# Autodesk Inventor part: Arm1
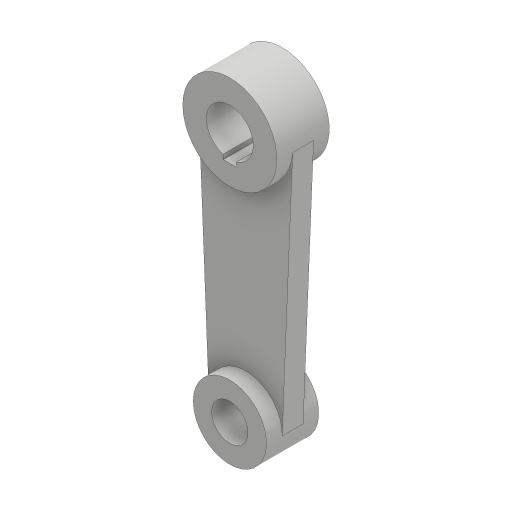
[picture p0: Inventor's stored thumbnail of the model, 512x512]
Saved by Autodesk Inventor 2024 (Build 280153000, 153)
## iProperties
Created: 2016-05
Part Number: Arm1
Material: Generic
Document SubType Name: Modeling
Designer: CADCIM
Density: 1 g/cm^3
Appearance: Default
Author: CADCIM
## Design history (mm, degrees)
sketch "Sketch1"
  geometry: C1 r 56.25 at (0, 0); C2 r 28 at (0, 0); C3 r 43.75 at (0, -300); C4 r 21.75 at (0, -300); 1 further point
  constraints: 4 centre point, 3 coincident
  dimensions: "d0" = 112.5 diameter of C1; "d1" = 56 diameter of C2; "d2" = 87.5 diameter of C3; "d3" = 43.5 diameter of C4; "d4" = 300 distance of C4.centre C2.centre
extrude "Extrusion1" new body sketch "Sketch1" stored distance "d5" = 62.5; taper "d6" = 0 deg
sketch "Sketch2"
  geometry: L1 (56.201, -2.344)-(43.712, -301.823); L2 (-56.201, -2.344)-(-43.712, -301.823); A1 r 56.25 centre (0, 0) between (-56.201, -2.344) and (56.201, -2.344); A2 r 43.75 centre (0, -300) between (43.712, -301.823) and (-43.712, -301.823); 3 further points
  constraints: 4 end point, 4 point on circle, 2 centre point, 2 coincident
extrude "Extrusion2" join sketch "Sketch2" stored distance "d7" = 25; taper "d8" = 0 deg
sketch "Sketch3"
  geometry: L1 (0, 0)-(0, 99.622); L2 (-8, 26.833)-(8, 26.833); L3 (8, 26.833)-(8, 32.3); L4 (8, 32.3)-(-8, 32.3); L5 (-8, 32.3)-(-8, 26.833); L6 (0, 0)-(0, -28); A1 r 28 centre (0, 0) between (-8, 26.833) and (8, 26.833) reference
  constraints: 12 end point, 3 point on circle, 2 parallel, 2 vertical, 1 horizontal, 1 perpendicular, 1 other
  dimensions: "d10" = 16 distance of L3.end L4.end; "d11" = 60.3 distance from line of L4 L6.end
extrude "Extrusion3" cut sketch "Sketch3" extent not by distance; stored distance "d12" = 25; taper "d13" = 0 deg
fillet "Fillet1" dims "d14" = 0.4
body "Solid1"
